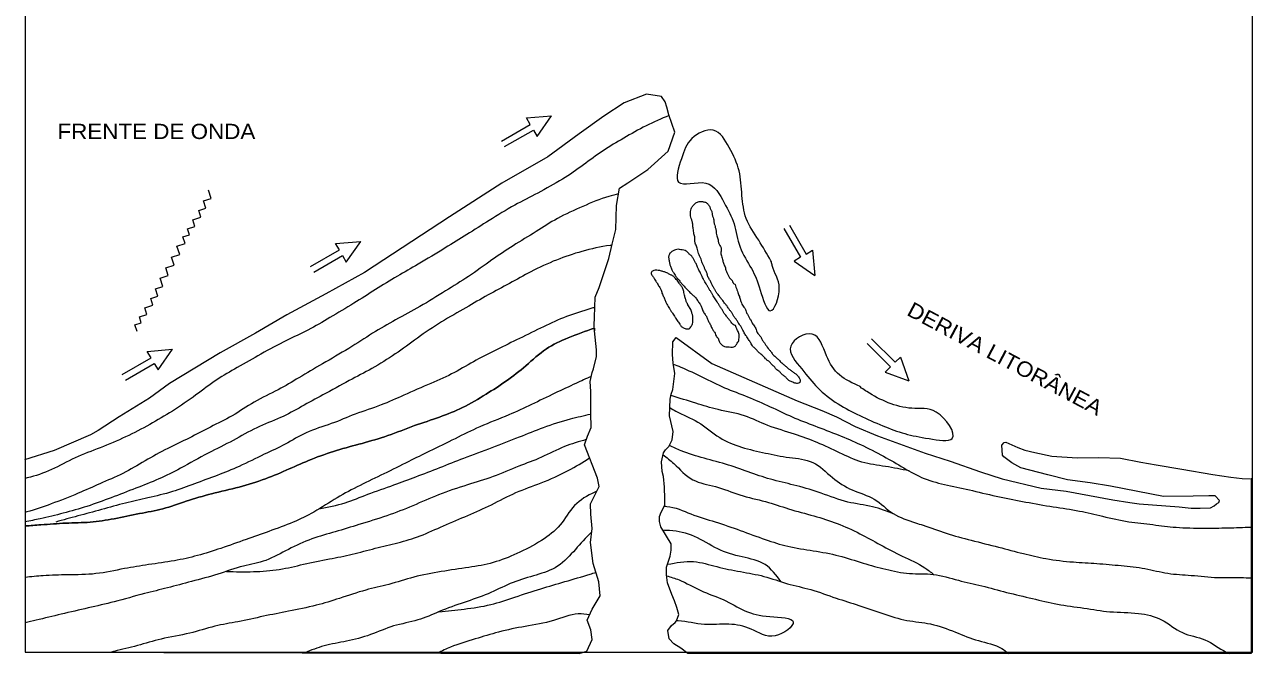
# Model space of a CAD drawing. Extents: x 32 to 150, y 1 to 212.
# Drawn here: x 32.1 to 128.9, y 55.2 to 104.8 of the extents above; entities that cross this region are included whole.
import ezdxf
from ezdxf.enums import TextEntityAlignment as Align

# ---------------------------------------------------------------- set-up
doc = ezdxf.new("R2010")
doc.units = 0
doc.header["$LTSCALE"] = 0.48
doc.layers.add('1', color=7, linetype='Continuous', lineweight=13)
doc.layers.add('44', color=7, linetype='Continuous', lineweight=13)

msp = doc.modelspace()

# ---------------------------------------------------------------- linework, layer by layer
at = {"layer": '1'}
for p, q in [((87.0048, 86.8121), (87.0043, 86.6924)), ((90.989, 86.0469), (90.9454, 86.149)), ((84.6319, 82.3098), (84.3995, 82.6739)), ((77.0391, 80.8339), (77.057, 80.6275)), ((88.146, 81.0392), (88.0387, 81.0572)), ((98.073, 76.1124), (97.965, 76.2299)), ((32.1837, 70.6764), (32.1837, 65.2423)), ((32.1837, 65.2408), (32.1837, 55.2831)), ((128.7773, 55.1909), (84.4035, 55.1909))]:
    msp.add_line(p, q, dxfattribs=at)
msp.add_lwpolyline([(32.1837, 55.2831), (128.8829, 55.2831), (128.8829, 166.2104), (32.1837, 166.2104)], close=True, dxfattribs=at)
for points in [[(77.057, 80.6275), (77.0212, 81.0404), (77.0345, 81.7036), (77.0884, 83.2811), (77.4126, 84.0274), (78.1653, 86.318), (78.4312, 87.4549), (78.7194, 88.614), (78.7794, 90.4888), (79.0278, 91.855), (79.6764, 92.272), (81.2432, 93.3273), (82.8399, 94.7708), (83.3784, 96.2892), (82.8982, 97.6526), (82.7336, 98.2521), (82.6095, 98.6674), (82.331, 99.087), (81.1426, 99.28), (79.3846, 98.596), (77.7736, 97.542), (75.8468, 96.1534), (73.3817, 94.3447), (69.741, 92.271), (65.6245, 89.5925), (58.9348, 85.2229), (55.8762, 83.5451), (52.7959, 81.8907), (50.3381, 80.4481), (47.5466, 78.8773), (43.5681, 76.4696), (41.9769, 75.3006), (39.5848, 73.8333), (37.9513, 72.757), (37.3487, 72.4303), (34.4754, 71.1821), (32.1422, 70.4455)], [(69.7107, 95.5758), (71.9784, 96.8851), (71.6831, 97.3966), (73.6593, 97.5624)], [(69.9645, 95.1362), (72.2322, 96.4454), (72.5276, 95.9338), (73.6593, 97.5624)], [(44.7907, 87.5087), (44.6247, 88.0215), (45.1303, 88.1876), (44.9779, 88.6528), (45.5707, 88.8464), (45.4024, 89.3618), (46.0416, 89.5702), (45.8686, 90.101), (46.4316, 90.2832), (46.2426, 90.8616), (46.8353, 91.0552), (46.6257, 91.6958)], [(91.9688, 88.6861), (93.278, 86.4183), (92.7665, 86.123), (94.395, 84.9913)], [(92.4084, 88.9399), (93.7177, 86.6721), (94.2292, 86.9675), (94.395, 84.9913)], [(41.0013, 80.578), (40.834, 81.092), (41.3398, 81.2571), (41.1874, 81.7222), (41.7803, 81.9171), (41.6116, 82.4311), (42.2534, 82.6397), (42.0794, 83.1703), (42.6411, 83.3526), (42.4532, 83.9298), (43.0448, 84.1258), (42.8364, 84.764), (43.4614, 84.9691), (43.2621, 85.5762), (43.9336, 85.795), (43.7238, 86.4356), (44.3644, 86.6441), (44.1502, 87.3002), (44.7907, 87.5087)], [(54.676, 85.6846), (56.9437, 86.9938), (56.6483, 87.5054), (58.6245, 87.6711)], [(54.9298, 85.2449), (57.1975, 86.5541), (57.4929, 86.0426), (58.6245, 87.6711)], [(32.1837, 55.2831), (75.8371, 55.1909), (76.437, 55.3804), (76.8527, 56.2844), (76.7581, 57.065), (76.4639, 57.8054), (76.857, 58.687), (77.4961, 59.7221), (77.3858, 60.8236), (76.9516, 62.2773), (76.72, 63.9313), (76.8529, 65.0489), (76.7652, 66.1726), (76.7373, 66.9744), (77.4054, 68.3519), (77.2863, 69.0188), (76.2572, 71.6331), (76.4918, 72.3132), (76.7925, 72.9914), (76.7494, 74.1368), (76.7614, 75.8299), (76.7114, 76.6323), (76.8581, 77.3376), (76.9744, 77.6319), (77.2145, 78.5864), (77.203, 79.113), (77.057, 80.6275)], [(84.4035, 55.1909), (83.838, 55.6113), (83.2928, 55.9468), (82.9255, 56.3458), (82.8286, 57.0122), (83.1013, 57.3937), (83.3932, 57.6374), (83.5063, 57.7716), (83.6929, 58.2698), (83.5275, 58.8237), (83.3611, 59.3317), (83.1506, 59.841), (82.794, 60.7662), (82.7182, 61.3861), (82.7081, 61.9814), (83.013, 62.8654), (83.0884, 63.3211), (83.0986, 63.8242), (82.2647, 65.1745), (82.1628, 65.5892), (82.1706, 65.978), (82.3099, 66.3175), (82.5862, 66.8819), (82.5964, 67.3851), (82.5707, 68.3012), (82.4775, 69.1505), (82.375, 69.5423), (82.324, 70.2989), (82.4928, 71.0037), (82.6302, 71.2516), (82.9001, 71.4959), (83.1535, 72.0153), (83.233, 72.6767), (82.9491, 73.9203), (83.0195, 75.2227), (83.094, 75.6326), (83.2117, 75.9955), (83.3695, 77.2498), (83.2317, 78.0774), (83.2014, 78.7647), (83.2212, 79.7482), (83.4709, 80.0846), (86.2777, 78.0392), (93.0188, 75.1075), (94.9684, 74.3444), (96.1062, 73.8325), (97.5703, 73.0827), (99.3438, 72.3474), (101.0751, 71.7047), (103.0918, 70.9855), (105.0658, 70.336), (107.4557, 69.5151), (109.1668, 68.9645), (112.2426, 68.2161), (114.2029, 67.979), (117.8765, 67.3058), (119.2188, 67.0857), (119.9677, 66.9964), (123.0978, 66.75), (124.0674, 66.6547), (124.7735, 66.6352), (125.5909, 66.6585), (125.8594, 66.8342), (126.0612, 66.9888), (126.2401, 67.0983), (126.2874, 67.2572), (125.9413, 67.61), (125.4558, 67.6233), (124.2187, 67.5887), (121.8779, 67.5617), (117.6995, 68.3862), (116.0928, 68.6364), (114.3091, 68.8686), (112.7498, 69.2777), (110.6412, 69.8164), (109.9208, 70.2253), (109.2897, 70.6774), (109.1821, 70.8177), (109.1316, 71.5971), (109.3348, 71.8204), (109.4456, 71.8402), (110.3866, 71.4252), (110.9562, 71.2036), (111.7474, 71.0217), (113.0883, 70.733), (115.0729, 70.6096), (116.7734, 70.6314), (118.4946, 70.5841), (120.0778, 70.2658), (121.2877, 70.0494), (123.3123, 69.719), (125.7544, 69.2857), (127.1854, 69.086), (128.0662, 68.9702), (128.7062, 68.9526)], [(98.5213, 79.6316), (100.3728, 77.78), (99.9551, 77.3624), (101.8211, 76.6907)], [(98.8803, 79.9905), (100.7317, 78.139), (101.1495, 78.5567), (101.8211, 76.6907)], [(39.8391, 77.178), (42.1068, 78.4873), (41.8114, 78.9988), (43.7877, 79.1646)], [(40.0929, 76.7384), (42.3606, 78.0476), (42.656, 77.536), (43.7877, 79.1646)], [(128.7732, 68.9965), (128.7773, 56.0668), (128.7773, 55.1909)]]:
    msp.add_lwpolyline(points, dxfattribs=at)
for points in [[(82.9213, 97.5867), (81.1144, 96.7863), (79.3504, 95.8052), (77.7187, 94.8203), (76.1726, 93.6958), (74.5162, 92.5743), (72.5733, 91.4836), (70.7656, 90.5266), (68.7542, 89.3233), (66.9875, 88.2048), (65.2883, 87.1533), (63.1426, 85.8621), (61.512, 84.9231), (59.7906, 83.872), (58.091, 82.7975), (56.1914, 81.6598), (54.4715, 80.6775), (52.777, 79.8545), (50.7683, 78.7886), (48.8921, 77.7189), (47.2831, 76.7564), (45.6472, 75.5657), (43.789, 74.2896), (42.0015, 73.2404), (40.1051, 72.2628), (38.1006, 71.4026), (36.1197, 70.6106), (34.2684, 69.6775), (32.3563, 69.0207), (32.1837, 68.9778)], [(90.9454, 86.149), (89.9843, 87.7545), (89.0034, 89.4749), (88.6647, 91.2921), (88.4387, 93.2206), (87.6592, 95.0728), (86.4061, 96.4346), (84.7148, 95.7718), (83.8876, 94.1698), (83.6741, 92.3449), (85.8142, 92.2631), (87.2621, 90.7129), (88.0453, 89.0436), (88.5164, 87.2228), (89.4095, 85.5277), (90.104, 83.8379), (90.8876, 82.1916), (91.6082, 83.9796), (91.0479, 85.7571), (90.989, 86.0469)], [(78.9463, 91.407), (78.1758, 91.2149), (76.1286, 90.4246), (74.1223, 89.4729), (72.4457, 88.4435), (70.6348, 87.3263), (68.9562, 86.2055), (67.1196, 84.9059), (65.3082, 83.7658), (63.2964, 82.5397), (61.3765, 81.4942), (59.5666, 80.4227), (57.6881, 79.2387), (55.61, 78.0144), (53.7554, 76.9214), (52.1247, 75.9822), (50.2283, 75.0046), (48.5066, 73.9307), (46.7885, 73.0398), (45.1151, 72.1706), (43.4206, 71.3476), (41.6344, 70.3671), (39.8925, 69.3853), (38.0656, 68.566), (36.3723, 67.8116), (34.236, 66.9781), (32.3244, 66.3442), (32.1837, 66.3112)], [(93.2244, 76.5435), (93.0465, 76.4797), (92.7605, 76.5334), (92.5854, 76.6069), (92.3666, 76.7044), (92.1933, 76.8694), (92.02, 77.0344), (91.8026, 77.2005), (91.6734, 77.3643), (91.4992, 77.4835), (91.347, 77.6021), (91.2183, 77.7888), (91.0229, 77.9543), (90.8722, 78.1416), (90.6763, 78.2842), (90.5247, 78.4257), (90.395, 78.5666), (90.1565, 78.7791), (89.9827, 78.9212), (89.8098, 79.1091), (89.6802, 79.2499), (89.4853, 79.4384), (89.4003, 79.6009), (89.2288, 79.8573), (89.0578, 80.1367), (88.8864, 80.3931), (88.7374, 80.6718), (88.6312, 80.8807), (88.5025, 81.0674), (88.3311, 81.3238), (88.2028, 81.5333), (88.0305, 81.744), (87.9243, 81.9529), (87.7956, 82.1395), (87.6448, 82.3268), (87.495, 82.5597), (87.3442, 82.7469), (87.1506, 83.004), (86.9783, 83.2147), (86.7848, 83.4717), (86.6556, 83.6354), (86.549, 83.8215), (86.4424, 84.0075), (86.3146, 84.2399), (86.2089, 84.4716), (86.0811, 84.704), (85.9537, 84.9592), (85.8922, 85.1897), (85.7648, 85.445), (85.6808, 85.6532), (85.575, 85.885), (85.5125, 86.0698), (85.4505, 86.2775), (85.3443, 86.4864), (85.2386, 86.7181), (85.1765, 86.9258), (85.1365, 87.1328), (85.0106, 87.4567), (84.9495, 87.7101), (84.9541, 87.9388), (84.8723, 88.2614), (84.8544, 88.4679), (84.8144, 88.6749), (84.7979, 88.95), (84.7377, 89.2492), (84.6141, 89.6874), (84.5966, 89.9167), (84.6228, 90.1219), (84.6932, 90.326), (84.8293, 90.5052), (84.987, 90.6611), (85.2104, 90.7922), (85.5418, 90.806), (85.7836, 90.7535), (85.9795, 90.6109), (86.1293, 90.3779), (86.2135, 90.1696), (86.2975, 89.9614), (86.3154, 89.7549), (86.3996, 89.5466), (86.44, 89.3624), (86.4584, 89.1789), (86.52, 88.9483), (86.5604, 88.7642), (86.622, 88.5336), (86.6399, 88.3271), (86.6799, 88.1201), (86.7837, 87.7969), (86.8233, 87.5669), (87.0136, 87.1498), (87.0048, 86.8121)], [(78.409, 87.3602), (78.2744, 87.3447), (76.0571, 86.8795), (74.0564, 86.2023), (72.0285, 85.2742), (70.3541, 84.3591), (68.6577, 83.4447), (66.9152, 82.4401), (64.994, 81.3259), (63.0916, 80.051), (61.3441, 78.7947), (59.5107, 77.6553), (57.7251, 76.6975), (55.6488, 75.5648), (53.9745, 74.6498), (52.3011, 73.7804), (50.4304, 72.9853), (48.5776, 71.9837), (46.6146, 70.985), (44.4268, 69.7867), (42.7096, 68.9415), (40.9066, 68.2131), (38.9706, 67.4655), (37.0581, 66.7859), (35.1926, 66.2423), (33.3734, 65.8118), (32.1837, 65.5562)], [(88.0387, 81.0572), (87.8227, 81.292), (87.6935, 81.4557), (87.5211, 81.6665), (87.3492, 81.9001), (87.1984, 82.0873), (87.0922, 82.2962), (86.9419, 82.5063), (86.8353, 82.6922), (86.707, 82.9018), (86.5999, 83.0649), (86.4073, 83.3677), (86.3011, 83.5766), (86.1724, 83.7632), (86.0658, 83.9492), (85.9592, 84.1352), (85.8526, 84.3212), (85.7455, 84.4844), (85.6388, 84.6704), (85.5538, 84.8329), (85.448, 85.0646), (85.2785, 85.4126), (85.1727, 85.6443), (85.0459, 85.9224), (84.9177, 86.132), (84.8115, 86.3408), (84.6612, 86.5509), (84.4658, 86.7165), (84.2709, 86.905), (84.0736, 86.979), (83.8535, 87.008), (83.6558, 87.0592), (83.4337, 86.9967), (83.2558, 86.933), (83.0319, 86.7789), (82.8949, 86.5538), (82.8899, 86.3022), (82.9505, 86.0259), (83.0116, 85.7726), (83.1168, 85.5179), (83.1794, 85.3331), (83.3086, 85.1694), (83.3936, 85.0069), (83.5439, 84.7967), (83.7594, 84.539), (83.9103, 84.3518), (84.1695, 84.0701), (84.364, 83.8588), (84.4936, 83.7179), (84.7754, 83.4584), (84.9703, 83.27), (85.1638, 83.0129), (85.3353, 82.7565), (85.4419, 82.5705), (85.5462, 82.2701), (85.6313, 82.1076), (85.8027, 81.8511), (85.9094, 81.6651), (85.993, 81.434), (86.1424, 81.1781), (86.2481, 80.9463), (86.3754, 80.6911), (86.5041, 80.5045), (86.6521, 80.1801), (86.8029, 79.9929), (86.886, 79.7388), (87.0153, 79.5751), (87.189, 79.433), (87.3863, 79.3589), (87.651, 79.3516), (87.9158, 79.3443), (88.1158, 79.4074), (88.2519, 79.5868), (88.4119, 79.857), (88.4381, 80.0622), (88.4437, 80.3367), (88.3172, 80.6376), (88.212, 80.8922), (88.146, 81.0392)], [(87.0043, 86.6924), (87.0453, 86.531), (87.1482, 86.162), (87.2309, 85.8852), (87.3573, 85.5842), (87.3978, 85.4), (87.4823, 85.2146), (87.5885, 85.0057), (87.6947, 84.7968), (87.8891, 84.5855), (87.9737, 84.4001), (88.1254, 84.2586), (88.1879, 84.0738), (88.2715, 83.8427), (88.3336, 83.635), (88.46, 83.334), (88.5427, 83.0572), (88.6264, 82.826), (88.8181, 82.4775), (88.9472, 82.3137), (88.9876, 82.1296), (89.137, 81.8737), (89.2432, 81.6648), (89.3499, 81.4788), (89.5199, 81.1537), (89.713, 80.8738), (89.839, 80.55), (90.0104, 80.2935), (90.1832, 80.1056), (90.2458, 79.9209), (90.4181, 79.7102), (90.5248, 79.5242), (90.8042, 79.1503), (90.955, 78.9631), (91.1268, 78.7295), (91.3654, 78.517), (91.5604, 78.3285), (91.7985, 78.0932), (91.9938, 77.9276), (92.1892, 77.762), (92.3846, 77.5964), (92.5804, 77.4537), (92.7979, 77.2876), (92.9936, 77.1448), (93.1229, 76.9811), (93.2506, 76.7487), (93.2244, 76.5435)], [(84.3995, 82.6739), (84.385, 82.714), (84.2788, 82.9229), (84.2173, 83.1534), (84.1345, 83.4303), (84.0945, 83.6373), (84.0123, 83.9371), (83.8624, 84.1701), (83.7121, 84.3802), (83.605, 84.5434), (83.3673, 84.8016), (83.1941, 84.9665), (82.9753, 85.0641), (82.7568, 85.1846), (82.5597, 85.2587), (82.3184, 85.3339), (82.0545, 85.387), (81.8338, 85.393), (81.6118, 85.3305), (81.5194, 85.1271), (81.6472, 84.8947), (81.7753, 84.6853), (81.8824, 84.5221), (82.0107, 84.3126), (82.1817, 84.0333), (82.2879, 83.8244), (82.3917, 83.5012), (82.5407, 83.2225), (82.6454, 82.945), (82.7512, 82.7132), (82.9433, 82.3876), (83.05, 82.2016), (83.2007, 82.0144), (83.3078, 81.8512), (83.4572, 81.5953), (83.5643, 81.4322), (83.7574, 81.1522), (83.8861, 80.9657), (84.0603, 80.8464), (84.3016, 80.7711), (84.5007, 80.7886), (84.6359, 80.9221), (84.7499, 81.102), (84.8009, 81.4439), (84.8051, 81.6498), (84.766, 81.9026), (84.6824, 82.1337), (84.6319, 82.3098)], [(77.0605, 82.4652), (76.761, 82.3748), (74.8274, 81.7416), (73.023, 80.9445), (71.1275, 80.0127), (69.3658, 79.1459), (67.7149, 78.2989), (66.0175, 77.3387), (64.1455, 76.475), (62.0293, 75.5492), (60.2253, 74.775), (58.2016, 74.0528), (56.3098, 73.3039), (54.3302, 72.5804), (52.6783, 71.6876), (51.0283, 70.8864), (49.0441, 69.9341), (47.3298, 69.2262), (45.5281, 68.5664), (43.7935, 67.9505), (41.8626, 67.4545), (40.0881, 67.0456), (38.201, 66.5255), (36.3363, 66.0278), (34.6045, 65.549)], [(77.0391, 80.8339), (74.9702, 80.067), (73.2527, 79.199), (71.6362, 77.8705), (70.1108, 76.6767), (68.4999, 75.6226), (66.6461, 74.5753), (64.8426, 73.824), (62.864, 73.1462), (60.7506, 72.3577), (58.7291, 71.7498), (56.7307, 71.187), (54.7295, 70.4869), (52.9921, 69.7339), (51.1219, 68.9615), (49.0554, 68.309), (46.881, 67.7739), (44.8821, 67.1882), (43.0377, 66.5983), (41.1974, 66.2141), (39.2022, 65.8115), (37.3201, 65.5429), (35.3975, 65.4586), (33.4299, 65.3297), (32.184, 65.2412)], [(32.184, 65.2412), (33.4299, 65.3297), (35.3975, 65.4586), (37.3201, 65.5429), (39.2022, 65.8115), (41.1974, 66.2141), (43.0377, 66.5983), (44.8821, 67.1882), (46.881, 67.7739), (49.0554, 68.309), (51.1219, 68.9615), (52.9921, 69.7339), (54.7295, 70.4869), (56.7307, 71.187), (58.7291, 71.7498), (60.7506, 72.3577), (62.864, 73.1462), (64.8426, 73.824), (66.6461, 74.5753), (68.4999, 75.6226), (70.1108, 76.6767), (71.6362, 77.8705), (73.2527, 79.199), (74.9702, 80.067), (77.0391, 80.8339)], [(97.965, 76.2299), (96.3496, 77.1439), (95.3204, 78.6598), (94.1846, 80.3616), (92.5098, 79.4237), (93.3785, 77.6148), (94.6293, 76.1386), (96.2372, 74.8586), (97.9409, 73.9421), (99.7571, 73.1368), (101.4889, 72.5171), (103.4017, 72.1211), (105.2346, 72.1393), (103.9738, 74.2107), (102.037, 74.5158), (100.1913, 74.9557), (98.5088, 75.8259), (98.073, 76.1124)], [(83.2439, 78.0039), (83.8435, 77.763), (85.5495, 76.9609), (87.2991, 76.1347), (89.0951, 75.4215), (90.8898, 74.6398), (92.6178, 73.837), (94.4138, 73.1239), (96.2541, 72.4096), (98.0051, 71.6519), (99.819, 70.7323), (101.4123, 69.8188), (103.0291, 68.9734), (104.8514, 68.4655), (106.8295, 68.022), (108.9612, 67.5285), (111.0285, 67.1283), (113.1845, 66.7485), (115.2532, 66.4169), (117.0774, 66.0005), (119.1442, 65.5774), (121.0383, 65.3421), (122.8665, 65.1316), (125.0511, 65.0714), (126.9502, 65.0878), (128.7744, 65.1506)], [(76.7935, 77.0274), (75.5823, 76.4803), (73.9328, 75.7018), (72.0823, 74.8146), (70.2995, 73.9941), (68.0063, 73.0504), (66.0667, 72.1198), (64.0375, 71.123), (62.4096, 70.3211), (60.4469, 69.3454), (58.5739, 68.4359), (56.7658, 67.4559), (54.9328, 66.3392), (53.3049, 65.5374), (51.3915, 64.812), (49.5902, 64.1751), (47.6111, 63.4744), (45.7671, 62.9074), (43.9485, 62.4998), (41.911, 62.1898), (40.0059, 61.8761), (37.7679, 61.48), (35.536, 61.3814), (33.614, 61.3199), (32.1837, 61.1869)], [(101.833, 69.58), (99.9794, 69.927), (98.1098, 70.276), (96.3583, 71.0108), (94.5862, 71.8148), (92.8113, 72.4815), (90.7054, 73.1574), (88.866, 73.9174), (86.7785, 74.4097), (85.0224, 74.9158), (83.0732, 75.5176)], [(82.9841, 74.5681), (83.4424, 74.2957), (85.1911, 73.4237), (86.9108, 72.2092), (88.6397, 71.4522), (90.507, 70.9888), (92.3987, 70.6393), (94.2454, 70.2452), (95.789, 69.0584), (97.3589, 68.0769), (99.0882, 67.3427), (100.567, 66.2265), (102.3406, 65.4911), (102.9327, 65.2916), (104.7527, 64.6695), (106.7285, 64.1116), (108.8813, 63.5716), (110.836, 63.0602), (112.6164, 62.6679), (114.7748, 62.4025), (116.627, 62.2828), (118.5444, 62.1155), (120.4164, 61.8809), (122.2194, 61.5108), (124.0486, 61.346), (126.1426, 61.174), (127.975, 61.1693), (128.7756, 61.1411)], [(55.3363, 66.5777), (57.3984, 67.0723), (59.1779, 67.7327), (61.2463, 68.4766), (62.9813, 69.1154), (64.8505, 69.842), (66.7423, 70.5908), (68.9891, 71.4214), (71.1254, 72.255), (73.0393, 73.0033), (75.1504, 73.6774), (76.7522, 74.0594)], [(76.4006, 72.0489), (74.6868, 71.4933), (72.8594, 70.6511), (71.0788, 69.945), (69.0533, 69.1312), (67.0309, 68.4776), (64.7631, 67.6933), (62.7365, 66.8337), (60.6894, 66.0434), (58.4895, 65.3488), (56.6236, 64.7823), (54.7795, 64.2152), (52.9305, 63.3966), (51.1467, 62.5304), (49.3933, 62.0752), (47.3715, 61.4444), (45.3063, 60.8605), (43.3976, 60.3639), (41.6, 59.9099), (39.2025, 59.2666), (37.1614, 58.7736), (35.0319, 58.283), (33.0574, 57.8111), (32.1837, 57.592)], [(82.4569, 70.8536), (83.2926, 70.1578), (84.7903, 68.8808), (86.568, 68.3513), (88.4973, 67.6802), (90.5182, 67.1669), (92.3391, 66.5904), (94.337, 66.0319), (96.1574, 65.4326), (97.9516, 64.628), (99.568, 63.7596), (101.2941, 62.8653), (103.0639, 61.947), (103.7599, 61.4243)], [(100.688, 66.1688), (98.9439, 66.7517), (97.0085, 67.1254), (94.9031, 67.8242), (92.9939, 68.4031), (91.1266, 68.8664), (89.3714, 69.4182), (87.5955, 70.0392), (85.6854, 70.5725), (83.865, 71.1718), (82.9442, 71.5862)], [(48.0424, 61.6485), (50.1794, 61.6417), (52.2142, 61.8145), (54.1211, 62.2196), (56.1609, 62.644), (57.9565, 63.0064), (59.7766, 63.4826), (61.5516, 63.9143), (63.3069, 64.4609), (65.1555, 65.2567), (67.0707, 66.0736), (68.9202, 66.9152), (70.8603, 67.8686), (72.8408, 68.6378), (74.98, 69.6087), (76.6636, 70.6009)], [(77.2235, 67.9768), (77.0651, 67.9036), (75.4762, 66.8489), (74.3415, 65.324), (72.8819, 64.1056), (70.9178, 63.0614), (69.0711, 62.357), (67.1426, 61.9753), (64.9722, 61.6461), (62.7995, 61.2025), (60.8453, 60.6385), (59.0256, 60.1851), (56.9592, 59.5326), (55.1156, 58.9884), (52.9426, 58.5219), (50.9694, 58.1186), (48.9517, 57.6937), (47.1339, 57.3318), (45.158, 56.7912), (42.8966, 56.3272), (41.0315, 55.8064), (39.2119, 55.3531), (38.9124, 55.2689)], [(82.5463, 66.8005), (82.7388, 66.7862), (84.6476, 66.1844), (86.5558, 65.5598), (88.5293, 64.8874), (90.5019, 64.1695), (92.2796, 63.64), (94.2816, 63.2873), (96.3048, 62.8884), (98.2139, 62.3094), (99.9926, 61.8256), (101.8627, 61.4995), (103.7378, 61.425), (105.7155, 60.9586), (107.5612, 60.5187), (109.5159, 60.0072), (111.5593, 59.5161), (113.5153, 59.0732), (115.6066, 58.7638), (117.6542, 58.4786), (119.9035, 58.348), (121.7258, 57.8401), (123.3614, 56.8339), (125.1381, 56.2586), (126.8188, 55.297), (127.0396, 55.1909)], [(91.74, 60.8464), (90.4842, 62.2019), (88.6859, 62.8007), (86.7556, 63.426), (84.9209, 64.4148), (82.9653, 64.8806), (82.4372, 64.8952)], [(76.8205, 64.7768), (76.6225, 64.5747), (75.3808, 63.213), (73.9422, 61.9482), (72.2293, 61.3089), (70.4064, 60.6954), (68.6682, 59.8966), (66.7778, 59.2164), (64.8202, 58.4922), (63.1288, 57.8295), (61.2206, 57.3557), (59.3964, 56.6736), (57.5092, 56.1535), (55.7355, 55.7904), (54.2238, 55.2366)], [(82.7902, 62.2195), (84.8587, 62.4256), (86.6833, 62.032), (88.552, 61.6373), (90.3991, 61.266), (92.242, 60.689), (94.0873, 60.2262), (96.0829, 59.5533), (97.8817, 58.9775), (99.7675, 58.3305), (101.6555, 57.798), (103.5265, 57.5176), (105.4784, 56.8688), (107.2974, 56.2008), (109.1394, 55.578), (109.6756, 55.1909)], [(64.792, 58.4817), (66.7892, 58.6898), (68.8717, 59.0443), (70.7824, 59.6324), (72.8047, 60.2861), (74.7149, 60.8514), (76.6918, 61.4377), (77.1598, 61.5802)], [(82.7278, 61.3072), (83.7037, 60.9928), (85.4308, 60.1443), (87.1828, 59.4324), (88.8874, 58.5616), (90.865, 58.0952), (92.7112, 57.6782), (91.2759, 56.5735), (89.3879, 57.1061), (87.6294, 57.4978), (85.7083, 57.4821), (83.6387, 57.7679), (83.5087, 57.7781)], [(76.6533, 58.2302), (75.7674, 58.3051), (73.8141, 57.7868), (71.5748, 57.3221), (69.4904, 56.8761), (67.6468, 56.332), (65.7132, 55.6986), (64.6758, 55.2145)]]:
    msp.add_spline(points, degree=3, dxfattribs=at)
at = {"layer": '44'}
msp.add_lwpolyline([(32.1837, 55.2831), (128.8829, 55.2831), (128.8829, 166.2104), (32.1837, 166.2104)], close=True, dxfattribs=at)

# ---------------------------------------------------------------- texts
at = {"layer": '1', "width": 1.1}
msp.add_text('FRENTE DE ONDA', height=1.2, dxfattribs=at).set_placement((42.5288, 95.7393), align=Align.CENTER)
msp.add_text('DERIVA LITORÂNEA', height=1.2, rotation=332.063, dxfattribs=at).set_placement((109.1091, 77.8953), align=Align.CENTER)

doc.saveas('drawing.dxf')
